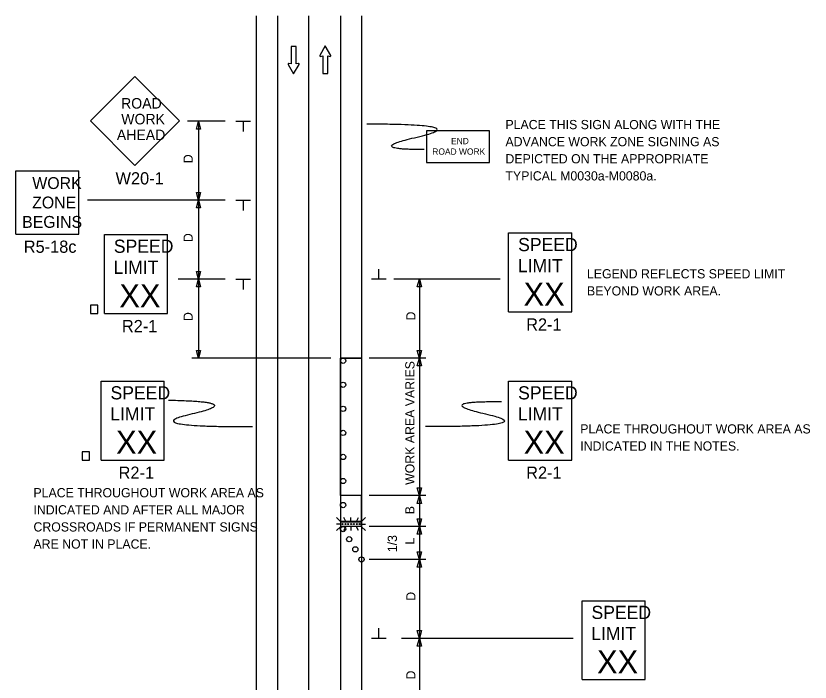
# Model space of a CAD drawing. Extents: x 16737 to 18470, y 7218 to 8193.
# Drawn here: x 16760 to 17364, y 7674 to 8181 of the extents above; entities that cross this region are included whole.
import ezdxf

# ---------------------------------------------------------------- set-up
doc = ezdxf.new("R2010")
doc.units = 0
for name, color, linetype in [('Level 6', 7, 'Continuous'), ('MT_SCRATCH_LEVEL_E', 7, 'Continuous'), ('PAVT_EDGE_EX', 7, 'Continuous'), ('TRAFFIC_SIGNS_PR', 7, 'Continuous'), ('TYPICAL_TEXT_DIMEN_PR', 7, 'Continuous')]:
    doc.layers.add(name, color=color, linetype=linetype)

msp = doc.modelspace()

# ---------------------------------------------------------------- linework, layer by layer
at = {"layer": 'Level 6'}
msp.add_lwpolyline([(16810.8, 7842.9), (16816.39, 7842.9), (16816.39, 7849.07), (16810.8, 7849.07)], close=True, dxfattribs=at)
at = {"layer": 'MT_SCRATCH_LEVEL_E'}
for p, q in [((16973.41, 8157.34), (16969.67, 8157.34)), ((16969.67, 8157.34), (16969.67, 8144.08)), ((16973.41, 8157.34), (16969.67, 8157.34)), ((16969.67, 8157.34), (16969.67, 8144.08)), ((16973.41, 8144.08), (16973.41, 8157.34)), ((16973.41, 8144.08), (16973.41, 8157.34)), ((16995.57, 8157.71), (16991.46, 8150.47)), ((16995.57, 8157.71), (16991.46, 8150.47)), ((16999.72, 8150.47), (16995.57, 8157.71)), ((16999.72, 8150.47), (16995.57, 8157.71)), ((16991.94, 8149.79), (16993.72, 8150.1)), ((16991.94, 8149.79), (16993.72, 8150.1)), ((16993.72, 8150.1), (16993.72, 8136.85)), ((16993.72, 8150.1), (16993.72, 8136.85)), ((16997.46, 8136.85), (16997.46, 8150.1)), ((16997.46, 8150.1), (16999.24, 8149.79)), ((16997.46, 8136.85), (16997.46, 8150.1)), ((16997.46, 8150.1), (16999.24, 8149.79)), ((16967.42, 8143.72), (16971.56, 8136.47)), ((16967.42, 8143.72), (16971.56, 8136.47)), ((16969.67, 8144.08), (16967.9, 8144.4)), ((16969.67, 8144.08), (16967.9, 8144.4)), ((16971.56, 8136.47), (16975.67, 8143.72)), ((16971.56, 8136.47), (16975.67, 8143.72)), ((16975.19, 8144.4), (16973.41, 8144.08)), ((16975.19, 8144.4), (16973.41, 8144.08)), ((16993.72, 8136.85), (16997.46, 8136.85)), ((16993.72, 8136.85), (16997.46, 8136.85))]:
    msp.add_line(p, q, dxfattribs=at)
for centre, start, end in [((16991.87, 8150.25), 150.42484, 279.96381), ((16991.87, 8150.25), 150.42484, 279.96381), ((16999.31, 8150.25), 260.03619, 29.77312), ((16999.31, 8150.25), 260.03619, 29.77312), ((16967.82, 8143.94), 80.03619, 209.77312), ((16967.82, 8143.94), 80.03619, 209.77312), ((16975.27, 8143.94), 330.42484, 99.96381), ((16975.27, 8143.94), 330.42484, 99.96381)]:
    msp.add_arc(centre, 0.463, start, end, dxfattribs=at)
at = {"layer": 'PAVT_EDGE_EX'}
for p, q in [((16943.15, 8180.56), (16943.15, 7445.4)), ((16959.15, 8180.56), (16959.15, 7445.4)), ((16983.15, 7383.56), (16983.15, 8180.56)), ((17007.15, 8180.56), (17007.15, 7445.4)), ((17023.15, 8180.56), (17023.15, 7445.4)), ((17007.15, 7815.82), (17007.15, 7920.41)), ((17007.15, 7920.41), (17023.15, 7920.41)), ((17023.15, 7920.41), (17023.15, 7815.82)), ((17023.15, 7815.82), (17007.15, 7815.82)), ((17023.15, 7815.82), (17007.15, 7815.82)), ((17007.15, 7815.82), (17007.15, 7796.12)), ((17023.15, 7796.12), (17023.15, 7815.82)), ((17007.15, 7796.12), (17023.15, 7796.12))]:
    msp.add_line(p, q, dxfattribs=at)
for points in [[(16983.15, 8145.4), (16983.15, 8170.4)], [(16983.15, 8045.4), (16983.15, 8070.4)], [(16983.15, 7945.4), (16983.15, 7970.4)], [(16983.15, 7845.4), (16983.15, 7870.4)], [(16983.15, 7745.4), (16983.15, 7770.4)]]:
    msp.add_lwpolyline(points, dxfattribs=at)
at = {"layer": 'TRAFFIC_SIGNS_PR'}
for p, q in [((16850.86, 8134.6), (16816.92, 8100.66)), ((16884.8, 8100.66), (16850.86, 8134.6)), ((16816.92, 8100.66), (16850.86, 8066.72)), ((16850.86, 8066.72), (16884.8, 8100.66)), ((16760.27, 8014.73), (16760.27, 8062.73)), ((16760.27, 8062.73), (16808.27, 8062.73)), ((16808.27, 8014.73), (16808.27, 8062.73)), ((16760.27, 8014.73), (16808.27, 8014.73)), ((16827.56, 8014.36), (16875.56, 8014.36)), ((16827.56, 7954.36), (16827.56, 8014.36)), ((16875.56, 7954.36), (16875.56, 8014.36)), ((17135.06, 8015.61), (17183.06, 8015.61)), ((17135.06, 7955.61), (17135.06, 8015.61)), ((17183.06, 7955.61), (17183.06, 8015.61)), ((16827.56, 7954.36), (16875.56, 7954.36)), ((17135.06, 7955.61), (17183.06, 7955.61)), ((17023.15, 7920.41), (17007.15, 7920.41)), ((17009.15, 7918.39), (17009.15, 7918.39)), ((16825.05, 7902.9), (16873.05, 7902.9)), ((16825.05, 7842.9), (16825.05, 7902.9)), ((16873.05, 7842.9), (16873.05, 7902.9)), ((17135.06, 7902.9), (17183.06, 7902.9)), ((17135.06, 7842.9), (17135.06, 7902.9)), ((17183.06, 7842.9), (17183.06, 7902.9)), ((16825.05, 7842.9), (16873.05, 7842.9)), ((17135.06, 7842.9), (17183.06, 7842.9)), ((17023.15, 7815.82), (17007.15, 7815.82)), ((17004.26, 7799.07), (17007.08, 7796.25)), ((17007.08, 7794.22), (17004.26, 7794.22)), ((17023.15, 7796.12), (17007.15, 7796.12)), ((17008.72, 7794.22), (17008.72, 7794.22)), ((17011.35, 7796.25), (17009.72, 7799.07)), ((17010.9, 7794.22), (17010.9, 7794.22)), ((17013.07, 7794.22), (17013.07, 7794.22)), ((17015.17, 7796.25), (17015.17, 7799.07)), ((17015.24, 7794.22), (17015.24, 7794.22)), ((17017.42, 7794.22), (17017.42, 7794.22)), ((17019.3, 7796.25), (17020.93, 7799.07)), ((17019.59, 7794.22), (17019.59, 7794.22)), ((17021.76, 7794.22), (17021.76, 7794.22)), ((17023.25, 7796.25), (17026.08, 7799.07)), ((17023.25, 7794.22), (17026.08, 7794.22)), ((17004.26, 7789.37), (17007.08, 7792.19)), ((17009.7, 7789.37), (17011.33, 7792.19)), ((17015.17, 7792.19), (17015.17, 7789.37)), ((17020.96, 7789.37), (17019.33, 7792.19)), ((17023.25, 7792.19), (17026.08, 7789.37)), ((17190.88, 7735.96), (17238.88, 7735.96)), ((17190.88, 7675.96), (17190.88, 7735.96)), ((17238.88, 7675.96), (17238.88, 7735.96)), ((17190.88, 7675.96), (17238.88, 7675.96))]:
    msp.add_line(p, q, dxfattribs=at)
for points in [[(17072.52, 8069.07), (17120.52, 8069.07), (17120.52, 8093.07), (17072.52, 8093.07)], [(16816.95, 7954.36), (16822.54, 7954.36), (16822.54, 7960.53), (16816.95, 7960.53)], [(17023.02, 7792.42), (17007.32, 7792.42), (17007.32, 7796.02), (17023.02, 7796.02)]]:
    msp.add_lwpolyline(points, close=True, dxfattribs=at)
for centre, radius in [((17009.15, 7918.39), 2), ((17009.15, 7900.1), 2), ((17009.15, 7881.81), 2), ((17009.15, 7863.53), 2), ((17009.15, 7845.24), 2), ((17009.15, 7826.96), 2), ((17009.15, 7808.67), 2), ((17008.74, 7794.22), 0.379), ((17010.89, 7794.22), 0.379), ((17013.07, 7794.22), 0.379), ((17015.24, 7794.22), 0.379), ((17017.42, 7794.22), 0.379), ((17019.59, 7794.22), 0.379), ((17021.76, 7794.22), 0.379), ((17009.14, 7790.38), 2), ((17009.15, 7790.39), 2), ((17013.81, 7782.69), 2), ((17018.48, 7774.99), 2), ((17023.15, 7767.3), 2)]:
    msp.add_circle(centre, radius, dxfattribs=at)
for points in [[(17070.78, 8078.89), (17023.55, 8078.89), (17108.57, 8098.24), (17027.09, 8098.24)], [(16876.28, 7888.4), (16936.27, 7887.45), (16851.25, 7868.11), (16940.17, 7868.26)], [(17129.54, 7887.08), (17075.7, 7887.45), (17160.73, 7868.11), (17071.81, 7868.26)]]:
    msp.add_open_spline(points, degree=2, dxfattribs=at)
at = {"layer": 'TYPICAL_TEXT_DIMEN_PR'}
for p, q in [((16919.43, 8100.41), (16890.7, 8100.41)), ((16897.58, 8094.55), (16899.15, 8100.41)), ((16899.15, 8100.41), (16900.73, 8094.55)), ((16899.15, 8100.41), (16899.15, 8040.41)), ((16927.47, 8100.41), (16938.72, 8100.41)), ((16933.1, 8100.41), (16933.1, 8092.63)), ((16899.15, 8094.55), (16897.58, 8094.55)), ((16900.73, 8094.55), (16899.15, 8094.55)), ((16899.15, 8040.41), (16897.58, 8046.28)), ((16897.58, 8046.28), (16899.15, 8046.28)), ((16899.15, 8046.28), (16900.73, 8046.28)), ((16900.73, 8046.28), (16899.15, 8040.41)), ((16919.43, 8040.41), (16814.69, 8040.41)), ((16897.58, 8034.55), (16899.15, 8040.41)), ((16899.15, 8040.41), (16900.73, 8034.55)), ((16899.15, 8040.41), (16899.15, 7980.41)), ((16927.47, 8040.41), (16938.72, 8040.41)), ((16933.1, 8040.41), (16933.1, 8032.63)), ((16899.15, 8034.55), (16897.58, 8034.55)), ((16900.73, 8034.55), (16899.15, 8034.55)), ((17036.27, 7980.28), (17036.27, 7988.07)), ((16899.15, 7980.41), (16897.58, 7986.28)), ((16897.58, 7986.28), (16899.15, 7986.28)), ((16899.15, 7986.28), (16900.73, 7986.28)), ((16900.73, 7986.28), (16899.15, 7980.41)), ((16919.43, 7980.41), (16883.8, 7980.41)), ((16897.58, 7974.55), (16899.15, 7980.41)), ((16899.15, 7974.55), (16897.58, 7974.55)), ((16899.15, 7980.41), (16900.73, 7974.55)), ((16899.15, 7980.03), (16899.15, 7920.41)), ((16900.73, 7974.55), (16899.15, 7974.55)), ((16927.47, 7980.41), (16938.72, 7980.41)), ((16933.1, 7980.41), (16933.1, 7972.63)), ((17041.89, 7980.28), (17030.64, 7980.28)), ((17128.6, 7980.39), (17047.81, 7980.39)), ((17065.58, 7974.52), (17067.15, 7980.39)), ((17067.15, 7974.52), (17065.58, 7974.52)), ((17067.15, 7980.39), (17068.73, 7974.52)), ((17067.15, 7980.39), (17067.15, 7920.93)), ((17068.73, 7974.52), (17067.15, 7974.52)), ((16899.15, 7920.41), (16897.58, 7926.28)), ((16897.58, 7926.28), (16899.15, 7926.28)), ((16899.15, 7920.41), (16897.58, 7926.28)), ((16897.58, 7926.28), (16899.15, 7926.28)), ((16899.15, 7926.28), (16900.73, 7926.28)), ((16900.73, 7926.28), (16899.15, 7920.41)), ((16899.15, 7926.28), (16900.73, 7926.28)), ((16900.73, 7926.28), (16899.15, 7920.41)), ((17067.15, 7920.39), (17065.58, 7926.25)), ((17065.58, 7926.25), (17067.15, 7926.25)), ((17067.15, 7926.25), (17068.73, 7926.25)), ((17068.73, 7926.25), (17067.15, 7920.39)), ((16999.85, 7920.41), (16894.15, 7920.41)), ((17072.15, 7920.39), (17028.88, 7920.39)), ((17065.58, 7914.52), (17067.15, 7920.39)), ((17067.15, 7920.39), (17067.15, 7815.82)), ((17067.15, 7920.39), (17068.73, 7914.52)), ((17067.15, 7914.52), (17065.58, 7914.52)), ((17068.73, 7914.52), (17067.15, 7914.52)), ((17067.15, 7815.82), (17065.58, 7821.69)), ((17065.58, 7821.69), (17067.15, 7821.69)), ((17067.15, 7821.69), (17068.73, 7821.69)), ((17068.73, 7821.69), (17067.15, 7815.82)), ((17072.15, 7815.82), (17028.88, 7815.82)), ((17065.58, 7809.96), (17067.15, 7815.82)), ((17065.58, 7809.96), (17067.15, 7815.82)), ((17067.15, 7815.82), (17067.15, 7792.39)), ((17067.15, 7815.82), (17068.73, 7809.96)), ((17067.15, 7815.82), (17068.73, 7809.96)), ((17067.15, 7809.96), (17065.58, 7809.96)), ((17067.15, 7809.96), (17065.58, 7809.96)), ((17068.73, 7809.96), (17067.15, 7809.96)), ((17068.73, 7809.96), (17067.15, 7809.96)), ((17067.15, 7792.39), (17065.58, 7798.25)), ((17065.58, 7798.25), (17067.15, 7798.25)), ((17067.15, 7798.25), (17068.73, 7798.25)), ((17068.73, 7798.25), (17067.15, 7792.39)), ((17072.15, 7792.39), (17028.88, 7792.39)), ((17065.58, 7786.53), (17067.15, 7792.39)), ((17067.15, 7792.39), (17067.15, 7767.3)), ((17067.15, 7792.39), (17068.73, 7786.53)), ((17067.15, 7786.53), (17065.58, 7786.53)), ((17068.73, 7786.53), (17067.15, 7786.53)), ((17067.15, 7767.3), (17065.58, 7773.16)), ((17065.58, 7773.16), (17067.15, 7773.16)), ((17067.15, 7773.16), (17068.73, 7773.16)), ((17068.73, 7773.16), (17067.15, 7767.3)), ((17072.15, 7767.3), (17028.88, 7767.3)), ((17065.58, 7761.44), (17067.15, 7767.3)), ((17067.15, 7767.3), (17068.73, 7761.44)), ((17067.15, 7767.3), (17067.15, 7707.85)), ((17067.15, 7761.44), (17065.58, 7761.44)), ((17068.73, 7761.44), (17067.15, 7761.44)), ((17036.27, 7707.3), (17036.27, 7715.08)), ((17067.15, 7707.3), (17065.58, 7713.16)), ((17065.58, 7713.16), (17067.15, 7713.16)), ((17067.15, 7713.16), (17068.73, 7713.16)), ((17068.73, 7713.16), (17067.15, 7707.3)), ((17041.89, 7707.3), (17030.64, 7707.3)), ((17184.13, 7707.3), (17053.58, 7707.3)), ((17065.58, 7701.44), (17067.15, 7707.3)), ((17067.15, 7707.3), (17068.73, 7701.44)), ((17067.15, 7707.3), (17067.15, 7647.3)), ((17067.15, 7701.44), (17065.58, 7701.44)), ((17068.73, 7701.44), (17067.15, 7701.44))]:
    msp.add_line(p, q, dxfattribs=at)

# ---------------------------------------------------------------- texts
at = {"layer": 'TRAFFIC_SIGNS_PR'}
for s, height, p in [('ROAD', 8, (16840.29, 8110.08)), ('WORK', 8, (16840.42, 8098.08)), ('PLACE THIS SIGN ALONG WITH THE', 7, (17132.66, 8094.44)), ('AHEAD', 8, (16837.06, 8086.08)), ('END', 4.789, (17091.27, 8082.99)), ('ADVANCE WORK ZONE SIGNING AS', 7, (17132.66, 8081.44)), ('ROAD WORK', 4.789, (17077.03, 8075)), ('DEPICTED ON THE APPROPRIATE', 7, (17132.66, 8068.44)), ('W20-1', 9.3, (16836.07, 8052.42)), ('TYPICAL M0030a-M0080a.', 7, (17132.66, 8055.44)), ('WORK', 9.021, (16772.77, 8048.94)), ('ZONE', 9.021, (16772.62, 8034.18)), ('BEGINS', 9.021, (16765.03, 8019.42)), ('SPEED', 10, (17142.27, 8001.69)), ('R5-18c', 9.3, (16766.28, 8000.43)), ('SPEED', 10, (16834.77, 8000.43)), ('LIMIT', 10, (16834.57, 7984.43)), ('LIMIT', 10, (17142.07, 7985.69)), ('LEGEND REFLECTS SPEED LIMIT', 7, (17194.66, 7980.99)), ('XX', 17.538, (16838.95, 7959.05)), ('XX', 17.538, (17146.45, 7960.31)), ('BEYOND WORK AREA.', 7, (17194.66, 7967.99)), ('R2-1', 9.3, (17148.41, 7941.31)), ('R2-1', 9.3, (16840.91, 7940.06)), ('SPEED', 10, (16832.26, 7888.98)), ('SPEED', 10, (17142.27, 7888.98)), ('LIMIT', 10, (16832.06, 7872.98)), ('LIMIT', 10, (17142.07, 7872.98)), ('PLACE THROUGHOUT WORK AREA AS', 7, (17189.55, 7863.07)), ('XX', 17.538, (16836.44, 7847.6)), ('XX', 17.538, (17146.45, 7847.6)), ('INDICATED IN THE NOTES.', 7, (17189.55, 7850.07)), ('R2-1', 9.3, (16838.4, 7828.6)), ('R2-1', 9.3, (17148.41, 7828.6)), ('PLACE THROUGHOUT WORK AREA AS', 7, (16773.64, 7814.55)), ('INDICATED AND AFTER ALL MAJOR', 7, (16773.64, 7801.55)), ('CROSSROADS IF PERMANENT SIGNS', 7, (16773.64, 7788.55)), ('ARE NOT IN PLACE.', 7, (16773.64, 7775.55)), ('SPEED', 10, (17198.09, 7722.04)), ('LIMIT', 10, (17197.89, 7706.04)), ('XX', 17.538, (17202.28, 7680.66))]:
    msp.add_text(s, height=height, dxfattribs=at).set_placement(p)
at = {"layer": 'TYPICAL_TEXT_DIMEN_PR'}
for s, p in [('D', (16894.78, 8068.55)), ('D', (16894.78, 8008.55)), ('D', (16894.78, 7948.55)), ('D', (17064.19, 7948.99)), ('WORK AREA VARIES', (17063.44, 7823.97)), ('B', (17063.44, 7801.67)), ('1/3', (17050.14, 7772.81)), ('L', (17063.44, 7778.6)), ('D', (17064.19, 7735.9)), ('D', (17064.19, 7676.03))]:
    msp.add_text(s, height=7, rotation=90, dxfattribs=at).set_placement(p)

doc.saveas('drawing.dxf')
